(* Logix 5000 project; controller MVI56E_SIE_v16 1756-L63 rev 16.7; software revision 16.04 *)

TASK MainTask (continuous, watchdog 500 ms) : MainProgram

MODULES
   Local : 1756-L63 (ICP 0, rev 16.7)
      SIE : vendor 1 type 0 code 15 (ICP 1, rev 1.1, Output RPI 5 ms)
END_MODULES

TYPE SIEBLOCKSTATS :   // This object is used to store the block transfer statistics for the MVI56E-SIE module.
STRUCT
   Read : INT;   // Total number of read block transfers
   Write : INT;   // Total number of write block transfers
   Parse : INT;   // Total number of blocks parsed
   Reserved : INT;   // Used internally for future use
   Cmd : INT;   // Total number of command blocks received
   Err : INT;   // Total number of block transfer errors
END_STRUCT
END_TYPE

TYPE SIECLIENTSTATS :   // This object is used to store the port statistics for an MVI56E-SIE port.
STRUCT
   CmdReq : INT;   // Total number of command list requests sent
   CmdResp : INT;   // Total number of command list responses received
   CmdErr : INT;   // Total number of command list errors
   Requests : INT;   // Total number of requests for port
   Responses : INT;   // Total number of responses for port
   ErrSent : INT;   // Total number of errors sent
   ErrRec : INT;   // Total number of errors received
   CfgErrWord : INT;   // Configuration Error Word
   CurErr : INT;   // Current Error code
   LastErr : INT;   // Last recorded error code
END_STRUCT
END_TYPE

TYPE SIECLOCKTYPE :   // Allows read/write of clock value between the module and processor
STRUCT
   Read : BOOL;   // Reads current time from the module
   Write : BOOL;   // Writes current time from the module
   Config : SIEDATETIME;   // Date and time configuration read or written between the module and processor
END_STRUCT
END_TYPE

TYPE SIECMDCONTROL :   // MVI56E-SIE Command Control
STRUCT
   ClientID : INT;   // Block5000 Client Identification by Index number 0 to 19
   CMDqty : INT;   // Block5000 command quantity
   CmdIndex : INT[16];   // Contains index in the command list for the 1st command to be entered into Command queue
   WriteCmdBits : INT[20];   // Command Bit control ClientID(0 to 19)
END_STRUCT
END_TYPE

TYPE SIECONTROL :   // Values used by program for data transfer operation between the module and the processor.
STRUCT
   BootTimer : TIMER;   // Timer used to clear both cold and warm boot requests
   ColdBoot : BOOL;   // Hardware reset of the Module
   WarmBoot : BOOL;   // Configuration data reset in the Module.
   ResetStatus : BOOL;   // Resets module status
   CmdID : INT;   // Command ID from 1 to 16
   CmdControl : SIECMDCONTROL;   // Holds Command Control statistics
   CmdControlPending : BOOL;   // Halts rung until Module is ready.
   CmdControlTrigger : BOOL;   // Command Control Trigger
   IPAddress : SIEIPADDRESS;   // Getting and Setting IP address to and from Module
END_STRUCT
END_TYPE

TYPE SIEDATA :   // Contains Read Data (data read from the module to the processor) and Write Data (data written from the processor to the module)
STRUCT
   ReadData : INT[600];   // Data read from module. Set array equal to the size set in the Configuration file.
   WriteData : INT[600];   // Data to write to module. Set array equal to the size set in the Configuration file.
END_STRUCT
END_TYPE

TYPE SIEDATETIME :   // Stores the date and time value
STRUCT
   Year : DINT;   // Displays module current year
   Month : DINT;   // Displays Module current month
   Day : DINT;   // Displays Module current day
   Hour : DINT;   // Displays Module current hour
   Minute : DINT;   // Displays Module current minute
   Seconds : DINT;   // Displays Module current second
END_STRUCT
END_TYPE

TYPE SIEETHERNET :   // Stores the MVI56E-SIE IP settings
STRUCT
   IP : INT[4];   // Module IP address
   Netmask : INT[4];   // Net mask used by the Module
   Gateway : INT[4];   // Gateway used by the module
END_STRUCT
END_TYPE

TYPE SIEETHERNETTYPE :   // Allows read/write Ethernet settings between the module and processor
STRUCT
   Read : BOOL;   // Enable Ethernet configuration transfer from module to processor
   Write : BOOL;   // Enable Ethernet configuration transfer from processor to module
   Config : SIEETHERNET;   // Module ethernet configurations ip, netmask and gateway
END_STRUCT
END_TYPE

TYPE SIEINITOUTDATA :   // Used to bring the Module into a known state after a restart operation.
STRUCT
   InitOutBlkIDLim : INT;   // Block Index Limit for ReadData size of the array
END_STRUCT
END_TYPE

TYPE SIEIPADDRESS :   // Data structure to get and set the IP address of the module.
STRUCT
   IPGetTrigger : BOOL;   // Gets IP Address
   IPReceived : INT[4];   // IP address received.
   IPSetTrigger : BOOL;   // Sets IP Address
   IPRequested : INT[4];   // IP address set.
END_STRUCT
END_TYPE

TYPE SIEMODULEDEF :   // This defines the whole module which includes all tags used in the program
STRUCT
   DATA : SIEDATA;   // Data read from module
   CONTROL : SIECONTROL;   // Client ,Server Status and blocks status
   STATUS : SIESTATUS;   // SIE Module control
   UTIL : SIEUTIL;   // Block statistics
END_STRUCT
END_TYPE

TYPE SIESTATUS :   // This status data is returned on each read block and can be used to detect proper module operation.
STRUCT
   PassCnt : INT;   // Program cycle counter
   ProductVersion : INT;   // This is used to pass the product version to the processor
   ProductCode : INT[2];   // This is used to pass the product Code to the processor
   BlockStats : SIEBLOCKSTATS;   // Block transfer statistics
   CmdBits : INT[20];   // Commands bits array to be used for 20 clients
   ClientStatsTrigger : BOOL;   // Get Client Status
   ClientID : INT;   // Client ID to get Status From
   ClientStatus : SIECLIENTSTATS[20];   // Client status data
   CmdErrorList : INT[16];   // Command Error List
END_STRUCT
END_TYPE

TYPE SIEUTIL :   // Values used by program for data transfer operation between the module and the processor.
STRUCT
   LastRead : INT;   // Index of last read block
   LastWrite : INT;   // Index of last write block
   BlockIndex : INT;   // Computed block offset for data table
   StatusIndex : INT;   // Computed block offset for status data
   ReadDataSizeGet : INT;   // Gets ReadData Array Length.
   WriteDataSizeGet : INT;   // Gets WriteData Array Length.
   ReadDataBlkCount : INT;   // Holds the value of the Block Counts of the Read Data Array.
   WriteDataBlkCount : INT;   // Holds the value of the Block Counts of the Write Data Array.
   RBTSremainder : INT;   // Holds remainder calculation value from the read array.
   WBTSremainder : INT;   // Holds remainder calculation value from the write array.
   IPsetPending : BOOL;   // Allows Setting module IP address
   IPgetPending : BOOL;   // Allows Getting module IP address
   InitOutputData : SIEINITOUTDATA;
   CheckInitialization : BOOL;   // Check Initialization trigger
   StatusSeqIndex : INT;   // Computed block offset for status data
END_STRUCT
END_TYPE

ADD_ON_INSTRUCTION AOI56ESIE   (* revision 1.2, ExecutePrescan *)
// MVI56E-SIE AddOn_Rung
// Revision note:
// v1_2 Fix to Memory Overflow bug in several Instructions
VAR_IN_OUT
   Connection_Input : INT[250]; {required}   // Input parameters.
   Connection_Output : INT[248]; {required}   // Output parameters.
   SIE : SIEMODULEDEF; {required}
END_VAR
VAR
   MJFAULTS : DINT[12];
END_VAR

ROUTINE Logic   (* ladder *)
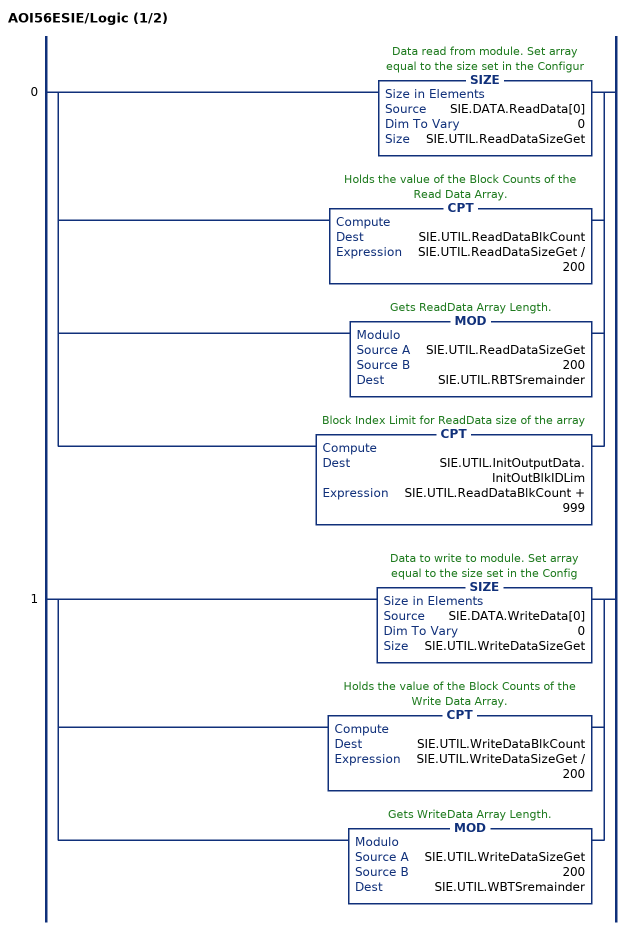
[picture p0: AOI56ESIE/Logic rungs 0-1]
   0: [SIZE(SIE.DATA.ReadData[0],0,SIE.UTIL.ReadDataSizeGet) ,CPT(SIE.UTIL.ReadDataBlkCount,SIE.UTIL.ReadDataSizeGet / 200) ,MOD(SIE.UTIL.ReadDataSizeGet,200,SIE.UTIL.RBTSremainder) ,CPT(SIE.UTIL.InitOutputData.InitOutBlkIDLim,SIE.UTIL.ReadDataBlkCount + 999) ];
   1: [SIZE(SIE.DATA.WriteData[0],0,SIE.UTIL.WriteDataSizeGet) ,CPT(SIE.UTIL.WriteDataBlkCount,SIE.UTIL.WriteDataSizeGet / 200) ,MOD(SIE.UTIL.WriteDataSizeGet,200,SIE.UTIL.WBTSremainder) ];
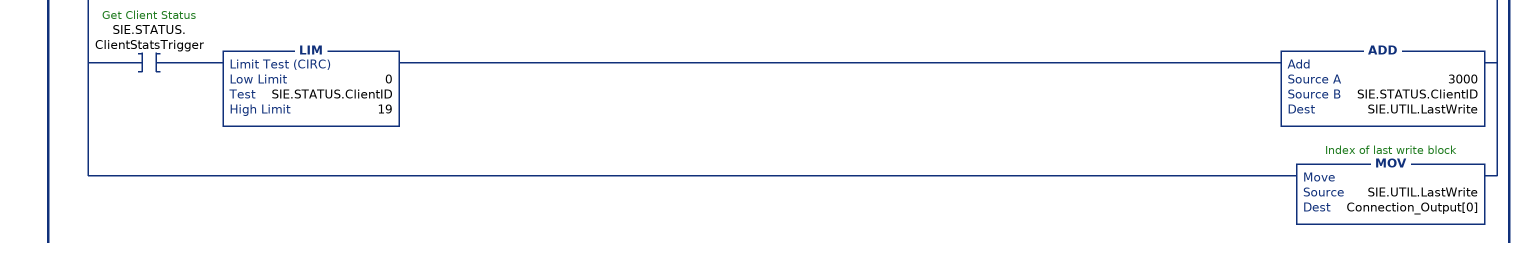
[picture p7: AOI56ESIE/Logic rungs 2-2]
   2: NEQ(Connection_Input[249],SIE.UTIL.LastRead)[MOV(Connection_Input[249],SIE.UTIL.LastRead) ,GEQ(SIE.UTIL.LastRead,1) [LEQ(SIE.UTIL.LastRead,SIE.UTIL.ReadDataBlkCount) [CPT(SIE.UTIL.BlockIndex,(SIE.UTIL.LastRead-1)*200) ,COP(Connection_Input[2],SIE.DATA.ReadData[SIE.UTIL.BlockIndex],200) ,COP(Connection_Input[202],SIE.STATUS.PassCnt,1) ,COP(Connection_Input[203],SIE.STATUS.BlockStats.Read,6) ,COP(Connection_Input[209],SIE.STATUS.CmdBits[0],20) ,COP(Connection_Input[229],SIE.STATUS.ProductCode[0],2) ,COP(Connection_Input[231],SIE.STATUS.ProductVersion,1) ] ,CMP(SIE.UTIL.LastRead - SIE.UTIL.ReadDataBlkCount = 1) GRT(SIE.UTIL.RBTSremainder,0) [CPT(SIE.UTIL.BlockIndex,(SIE.UTIL.LastRead - 1) * 200) ,COP(Connection_Input[2],SIE.DATA.ReadData[SIE.UTIL.BlockIndex],SIE.UTIL.RBTSremainder) ,COP(Connection_Input[202],SIE.STATUS.PassCnt,1) ,COP(Connection_Input[203],SIE.STATUS.BlockStats.Read,6) ,COP(Connection_Input[209],SIE.STATUS.CmdBits[0],20) ,COP(Connection_Input[229],SIE.STATUS.ProductCode[0],2) ,COP(Connection_Input[231],SIE.STATUS.ProductVersion,1) ] ] ,LIM(3000,SIE.UTIL.LastRead,3029) [CPT(SIE.UTIL.StatusIndex,SIE.UTIL.LastRead-3000) ,COP(Connection_Input[3],SIE.STATUS.ClientStatus[SIE.UTIL.StatusIndex].CmdReq,10) ,COP(Connection_Input[13],SIE.STATUS.CmdErrorList[0],16) ,OTU(SIE.STATUS.ClientStatsTrigger) ] ,EQU(SIE.UTIL.LastRead,9990) [COP(Connection_Input[2],SIE.CONTROL.IPAddress.IPRequested[0],4) ,OTU(SIE.UTIL.IPsetPending) ] ,EQU(SIE.UTIL.LastRead,9991) [COP(Connection_Input[2],SIE.CONTROL.IPAddress.IPReceived[0],4) ,OTU(SIE.UTIL.IPgetPending) ] ,XIC(SIE.CONTROL.CmdControlTrigger) LIM(5001,SIE.UTIL.LastRead,5016) LIM(1,Connection_Input[2],16) OTU(SIE.CONTROL.CmdControlTrigger) ,MOV(Connection_Input[1],SIE.UTIL.LastWrite) ,XIC(SIE.CONTROL.WarmBoot) [MOV(9998,SIE.UTIL.LastWrite) ,OTU(SIE.CONTROL.WarmBoot) ] ,XIC(SIE.CONTROL.ColdBoot) [MOV(9999,SIE.UTIL.LastWrite) ,OTU(SIE.CONTROL.ColdBoot) ] ,XIC(SIE.CONTROL.ResetStatus) [MOV(9997,SIE.UTIL.LastWrite) ,OTU(SIE.CONTROL.ResetStatus) ] ,XIC(SIE.CONTROL.IPAddress.IPSetTrigger) XIO(SIE.UTIL.IPsetPending) [COP(SIE.CONTROL.IPAddress.IPRequested[0],Connection_Output[1],4) ,MOV(9990,SIE.UTIL.LastWrite) ,OTU(SIE.CONTROL.IPAddress.IPSetTrigger) ,OTL(SIE.UTIL.IPsetPending) ] ,XIC(SIE.CONTROL.IPAddress.IPGetTrigger) XIO(SIE.UTIL.IPgetPending) [MOV(9991,SIE.UTIL.LastWrite) ,OTU(SIE.CONTROL.IPAddress.IPGetTrigger) ,OTL(SIE.UTIL.IPgetPending) ] ,XIC(SIE.CONTROL.CmdControlTrigger) LIM(1,SIE.CONTROL.CmdID,16) [LIM(0,SIE.CONTROL.CmdControl.ClientID,19) MOV(SIE.CONTROL.CmdControl.ClientID,Connection_Output[1]) ,COP(SIE.CONTROL.CmdControl.CmdIndex[0],Connection_Output[2],16) ,ADD(5000,SIE.CONTROL.CmdID,SIE.UTIL.LastWrite) ] ,GEQ(SIE.UTIL.LastWrite,1) [LEQ(SIE.UTIL.LastWrite,SIE.UTIL.WriteDataBlkCount) [CPT(SIE.UTIL.BlockIndex,(SIE.UTIL.LastWrite-1)*200) ,COP(SIE.DATA.WriteData[SIE.UTIL.BlockIndex],Connection_Output[1],200) ,COP(SIE.CONTROL.CmdControl.WriteCmdBits[0],Connection_Output[201],20) ] ,CMP(SIE.UTIL.LastWrite - SIE.UTIL.WriteDataBlkCount = 1) GRT(SIE.UTIL.WBTSremainder,0) [CPT(SIE.UTIL.BlockIndex,(SIE.UTIL.LastWrite - 1) * 200) ,COP(SIE.DATA.WriteData[SIE.UTIL.BlockIndex],Connection_Output[1],SIE.UTIL.WBTSremainder) ,COP(SIE.CONTROL.CmdControl.WriteCmdBits[0],Connection_Output[201],20) ] ] ,LIM(1000,SIE.UTIL.LastWrite,1024) LEQ(SIE.UTIL.LastWrite,SIE.UTIL.InitOutputData.InitOutBlkIDLim) [CPT(SIE.UTIL.BlockIndex,(SIE.UTIL.LastWrite-1000)*200) ,COP(SIE.DATA.ReadData[SIE.UTIL.BlockIndex],Connection_Output[1],200) ] ,[EQU(-1,SIE.UTIL.LastWrite) ,EQU(0,SIE.UTIL.LastWrite) ] [[EQU(SIE.STATUS.ProductCode[1],13637) GEQ(SIE.STATUS.ProductVersion,204) ,EQU(SIE.STATUS.ProductCode[1],13635) GEQ(SIE.STATUS.ProductVersion,113) ] [GEQ(SIE.UTIL.WriteDataSizeGet,200) COP(SIE.DATA.WriteData[0],Connection_Output[1],200) ,LES(SIE.UTIL.WriteDataSizeGet,200) COP(SIE.DATA.WriteData[0],Connection_Output[1],SIE.UTIL.WBTSremainder) ] ,COP(SIE.CONTROL.CmdControl.WriteCmdBits[0],Connection_Output[201],20) ] ,XIC(SIE.STATUS.ClientStatsTrigger) LIM(0,SIE.STATUS.ClientID,19) ADD(3000,SIE.STATUS.ClientID,SIE.UTIL.LastWrite) ,MOV(SIE.UTIL.LastWrite,Connection_Output[0]) ];
END_ROUTINE

ROUTINE Prescan   (* ladder *)
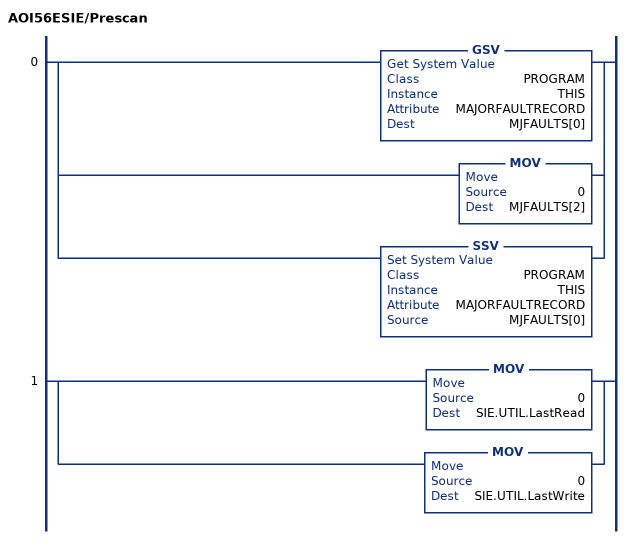
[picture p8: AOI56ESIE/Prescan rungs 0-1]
   0: [GSV(PROGRAM,THIS,MAJORFAULTRECORD,MJFAULTS[0]) ,MOV(0,MJFAULTS[2]) ,SSV(PROGRAM,THIS,MAJORFAULTRECORD,MJFAULTS[0]) ];
   1: [MOV(0,SIE.UTIL.LastRead) ,MOV(0,SIE.UTIL.LastWrite) ];
END_ROUTINE
END_ADD_ON_INSTRUCTION

ADD_ON_INSTRUCTION AOI56ESIE_OPTIONAL   (* revision 1.0 *)
// MVI56E-SIEOptional Add-On Ethernet/Clock
// Revision note:
// Release
VAR_IN_OUT
   MVI56SIEEthernet : SIEETHERNETTYPE; {required}   // MVI56E-SIE Rev2 Ethernet Settings
        .READ   // MVI56E-SIE Rev2 Ethernet Settings Enable Ethernet configuration transfer from module to processor
   MVI56SIEClock : SIECLOCKTYPE; {required}   // MVI56E-SIE Rev2 Clock Settings
   ReadEthernetMSG : MESSAGE; {required}   // Read Ethernet Settings Message
   WriteEthernetMSG : MESSAGE; {required}   // Write Ethernet Settings Message
   ReadClockMSG : MESSAGE; {required}   // Read Clock Settings Message
   WriteClockMSG : MESSAGE; {required}   // Write Clock Settings Message
END_VAR

ROUTINE Logic   (* ladder *)
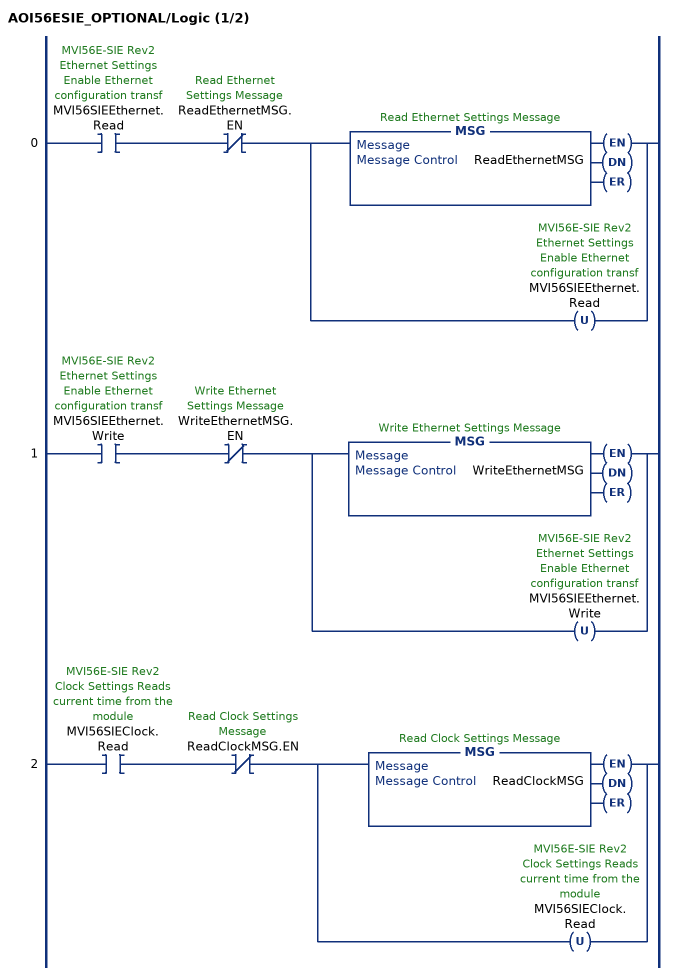
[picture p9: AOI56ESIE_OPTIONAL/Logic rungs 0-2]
   0: XIC(MVI56SIEEthernet.Read)XIO(ReadEthernetMSG.EN)[MSG(ReadEthernetMSG) ,OTU(MVI56SIEEthernet.Read) ];
   1: XIC(MVI56SIEEthernet.Write)XIO(WriteEthernetMSG.EN)[MSG(WriteEthernetMSG) ,OTU(MVI56SIEEthernet.Write) ];
   2: XIC(MVI56SIEClock.Read)XIO(ReadClockMSG.EN)[MSG(ReadClockMSG) ,OTU(MVI56SIEClock.Read) ];
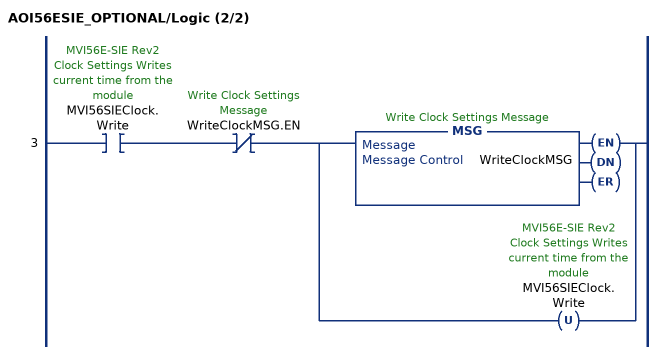
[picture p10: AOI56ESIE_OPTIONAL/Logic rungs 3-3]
   3: XIC(MVI56SIEClock.Write)XIO(WriteClockMSG.EN)[MSG(WriteClockMSG) ,OTU(MVI56SIEClock.Write) ];
END_ROUTINE
END_ADD_ON_INSTRUCTION

VAR_GLOBAL   (* controller tags *)
   AOI56ESIE_OPTIONAL : AOI56ESIE_OPTIONAL;
   AOI56SIE : AOI56ESIE;   // MVI56E-SIE AddOn_Rung
   MVI56ESIECLOCK : SIECLOCKTYPE;
   MVI56ESIEETHERNET : SIEETHERNETTYPE;
   READCLOCKMSG : MESSAGE;
        MessageParameters(ServiceCode := 16#000e, DestinationTag := MVI56ESIECLOCK.Config, ...)
   READETHERNETMSG : MESSAGE;
        MessageParameters(ServiceCode := 16#000e, DestinationTag := MVI56ESIEETHERNET.Config, ...)
   SIE : SIEMODULEDEF;
   WRITECLOCKMSG : MESSAGE;
        MessageParameters(ServiceCode := 16#0010, LocalElement := MVI56ESIECLOCK.Config, ...)
   WRITEETHERNETMSG : MESSAGE;
        MessageParameters(ServiceCode := 16#0010, LocalElement := MVI56ESIEETHERNET.Config, ...)
END_VAR

PROGRAM MainProgram   (* main routine MainRoutine *)

ROUTINE MainRoutine   (* ladder *)
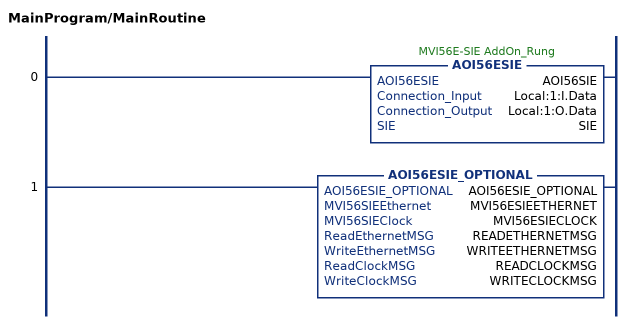
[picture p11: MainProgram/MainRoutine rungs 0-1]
   0: AOI56ESIE(AOI56SIE,Local:1:I.Data,Local:1:O.Data,SIE);
   1: AOI56ESIE_OPTIONAL(AOI56ESIE_OPTIONAL,MVI56ESIEETHERNET,MVI56ESIECLOCK,READETHERNETMSG,WRITEETHERNETMSG,READCLOCKMSG,WRITECLOCKMSG);
END_ROUTINE
END_PROGRAM
